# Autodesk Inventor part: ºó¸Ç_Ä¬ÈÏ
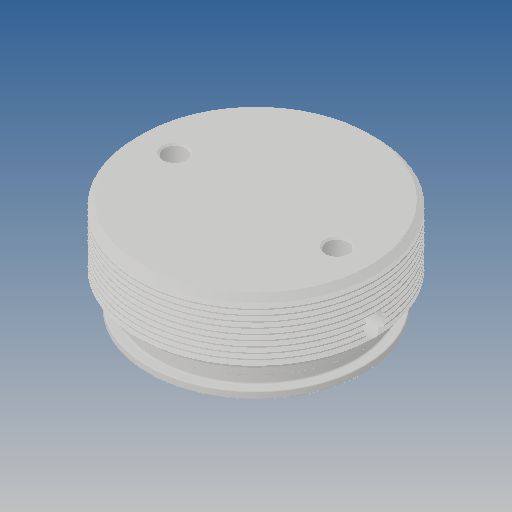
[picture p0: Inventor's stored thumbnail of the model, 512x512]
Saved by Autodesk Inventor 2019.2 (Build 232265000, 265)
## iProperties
Created: 2011-12
Part Number: ºó¸Ç_Ä¬ÈÏ
Material: Ogólny
Document SubType Name: Modeling
Designer: CADENGINEERING4
Density: 1 g/cm^3
Appearance: Domyślna
Author: CADENGINEERING4
Revision Number: ÈÎºÎ
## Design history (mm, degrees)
feature "NONE"
node "Bryła1"
